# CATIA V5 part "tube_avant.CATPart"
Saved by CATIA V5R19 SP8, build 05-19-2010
Part number: tube_avant
Bounding box of the stored display mesh (mm): x -450 to 450, y -20 to 20, z -20 to 20
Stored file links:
  U:\Thinkmotion\Assemblage final\tube_avant.CATPart
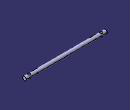
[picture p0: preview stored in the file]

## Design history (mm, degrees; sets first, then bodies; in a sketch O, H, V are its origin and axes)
Body1 (main body)
  Sketch1 on yz-plane, origin (0, 0, 0), H (0, 1, 0), V (0, 0, 1)
    circle A1 centre (0, 0) radius 20
    radius A1 = 20
  Pad1: profile Sketch1, direction (1, 0, 0), length 450
  Sketch2 on xy-plane, origin (5.3797, 3.2688, 0), H (1, 0, 0), V (0, 1, 0)
    point P1 (394.6203, -3.2688)
    reference projected line E1 (444.6203, 21.0919) -> (444.6203, -27.6294) from edge [face of Pad1 from Sketch1.A1 | end face of Pad1]
    distance E1 P1 = 50
  Hole1: placed by Sketch2, at (400, 0, 0) direction (0, 0, -1), diameter 30, through (limit type 6)
  Mirror1: of Pad1, Sketch1, about yz-plane
  Mirror2: of Hole1, about yz-plane
  Sketch3 on zx-plane, origin (-5.61, 0, -11.614), H (1, 0, 0), V (0, 0, -1)
    point P1 (-319.39, -11.614)
    reference intersected line E1 through (0, -11.614) direction (1, 0) from xy-plane
    reference intersected line E2 through (5.61, 0) direction (0, 1) from yz-plane
    distance P1 E2 = 325
    coincidence: P1 E1
  Hole2: placed by Sketch3, at (-325, 0, 0) direction (0, -1, 0), diameter 10, through (limit type 3)
  Mirror3: of Hole2, about yz-plane
  Sketch4 on xy-plane, origin (0, 0, 0), H (1, 0, 0), V (0, 1, 0)
    point P1 (295, -110)
    line L1 (295, -110) -> (355, -110)
    line L2 (355, -110) -> (355, -10)
    line L3 (355, -10) -> (295, -10)
    line L4 (295, -10) -> (295, -110)
    point P2 (355, -110)
    point P3 (355, -10)
    point P4 (295, -10)
    reference projected line E1 through (325, 0) direction (0, -1) from axis of face of Mirror3
    point P5 (-295, -110)
    point P6 (-355, -110)
    point P7 (-355, -10)
    point P8 (-295, -10)
    line L5 (-295, -110) -> (-355, -110)
    line L6 (-355, -110) -> (-355, -10)
    line L7 (-355, -10) -> (-295, -10)
    line L8 (-295, -10) -> (-295, -110)
    distance L3 H = 10
    distance L2 E1 = 30
    length L1 = 60
    horizontal: L1 H, L3 H
    vertical: L2 V, L4 V
    symmetry: P1 P5 V, P2 P6 V, P3 P7 V, P4 P8 V, L1 L5 V, L2 L6 V, L3 L7 V, L4 L8 V
  Pocket1: profile Sketch4, direction (0, 0, -1), length 60, mirrored extent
